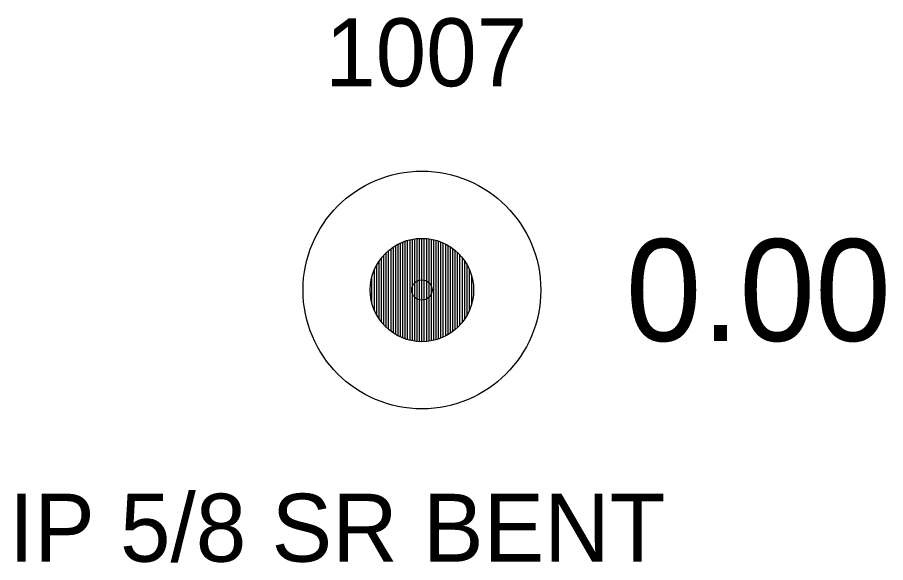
# Model space of a CAD drawing. Extents: x 1529475 to 1532053, y 876698 to 877911.
# Drawn here: x 1531508.37 to 1531521.15, y 877523.4 to 877531.43 of the extents above; entities that cross this region are included whole.
import ezdxf

# ---------------------------------------------------------------- set-up
doc = ezdxf.new("R2010")
doc.units = 0
for name, color, linetype in [('RD_EX_DV_Prop_txCode', 7, 'Continuous'), ('RD_EX_DV_PropPin', 7, 'Continuous'), ('RD_EX_TX_DV_Prop_ELEV', 7, 'Continuous'), ('RD_SMD_Locator', 7, 'Continuous')]:
    doc.layers.add(name, color=color, linetype=linetype)

msp = doc.modelspace()

# ---------------------------------------------------------------- linework, layer by layer
at = {"layer": 'RD_EX_DV_PropPin'}
for p, q in [((1531514.041, 877526.706), (1531514.041, 877528.121)), ((1531514.076, 877526.693), (1531514.076, 877528.134)), ((1531514.111, 877526.682), (1531514.111, 877528.145)), ((1531514.146, 877526.673), (1531514.146, 877528.155)), ((1531514.181, 877526.666), (1531514.181, 877528.162)), ((1531514.216, 877526.66), (1531514.216, 877528.168)), ((1531514.251, 877526.656), (1531514.251, 877528.172)), ((1531514.286, 877526.654), (1531514.286, 877528.174)), ((1531514.321, 877526.653), (1531514.321, 877528.175)), ((1531514.356, 877526.654), (1531514.356, 877528.174)), ((1531514.391, 877526.656), (1531514.391, 877528.172)), ((1531514.426, 877526.66), (1531514.426, 877528.168)), ((1531514.461, 877526.666), (1531514.461, 877528.162)), ((1531514.496, 877526.673), (1531514.496, 877528.155)), ((1531514.531, 877526.682), (1531514.531, 877528.145)), ((1531514.566, 877526.693), (1531514.566, 877528.134)), ((1531514.601, 877526.706), (1531514.601, 877528.121)), ((1531513.831, 877526.832), (1531513.831, 877527.996)), ((1531513.866, 877526.804), (1531513.866, 877528.024)), ((1531513.901, 877526.779), (1531513.901, 877528.048)), ((1531513.936, 877526.758), (1531513.936, 877528.07)), ((1531513.971, 877526.738), (1531513.971, 877528.09)), ((1531514.006, 877526.721), (1531514.006, 877528.107)), ((1531514.636, 877526.721), (1531514.636, 877528.107)), ((1531514.671, 877526.738), (1531514.671, 877528.09)), ((1531514.706, 877526.758), (1531514.706, 877528.07)), ((1531514.741, 877526.779), (1531514.741, 877528.048)), ((1531514.776, 877526.804), (1531514.776, 877528.024)), ((1531514.811, 877526.832), (1531514.811, 877527.996)), ((1531513.726, 877526.94), (1531513.726, 877527.888)), ((1531513.761, 877526.899), (1531513.761, 877527.929)), ((1531513.796, 877526.863), (1531513.796, 877527.965)), ((1531514.846, 877526.863), (1531514.846, 877527.965)), ((1531514.881, 877526.899), (1531514.881, 877527.929)), ((1531514.916, 877526.94), (1531514.916, 877527.888)), ((1531513.656, 877527.044), (1531513.656, 877527.783)), ((1531513.691, 877526.987), (1531513.691, 877527.84)), ((1531514.951, 877526.987), (1531514.951, 877527.84)), ((1531514.986, 877527.044), (1531514.986, 877527.783)), ((1531513.586, 877527.218), (1531513.586, 877527.61)), ((1531513.621, 877527.116), (1531513.621, 877527.712)), ((1531515.021, 877527.116), (1531515.021, 877527.712)), ((1531515.056, 877527.218), (1531515.056, 877527.61))]:
    msp.add_line(p, q, dxfattribs=at)
for radius in [1.75, 0.761]:
    msp.add_circle((1531514.321, 877527.414), radius, dxfattribs=at)
at = {"layer": 'RD_SMD_Locator'}
msp.add_circle((1531514.321, 877527.414), 0.15, dxfattribs=at)

# ---------------------------------------------------------------- texts
at = {"layer": 'RD_EX_DV_Prop_txCode'}
for s, p in [('1007', (1531512.896, 877530.414)), ('IP 5/8 SR BENT', (1531508.242, 877523.414))]:
    msp.add_text(s, height=1, dxfattribs=at).set_placement(p)
at = {"layer": 'RD_EX_TX_DV_Prop_ELEV'}
msp.add_text('0.00', height=1.5, dxfattribs=at).set_placement((1531517.321, 877526.664))

doc.saveas('drawing.dxf')
